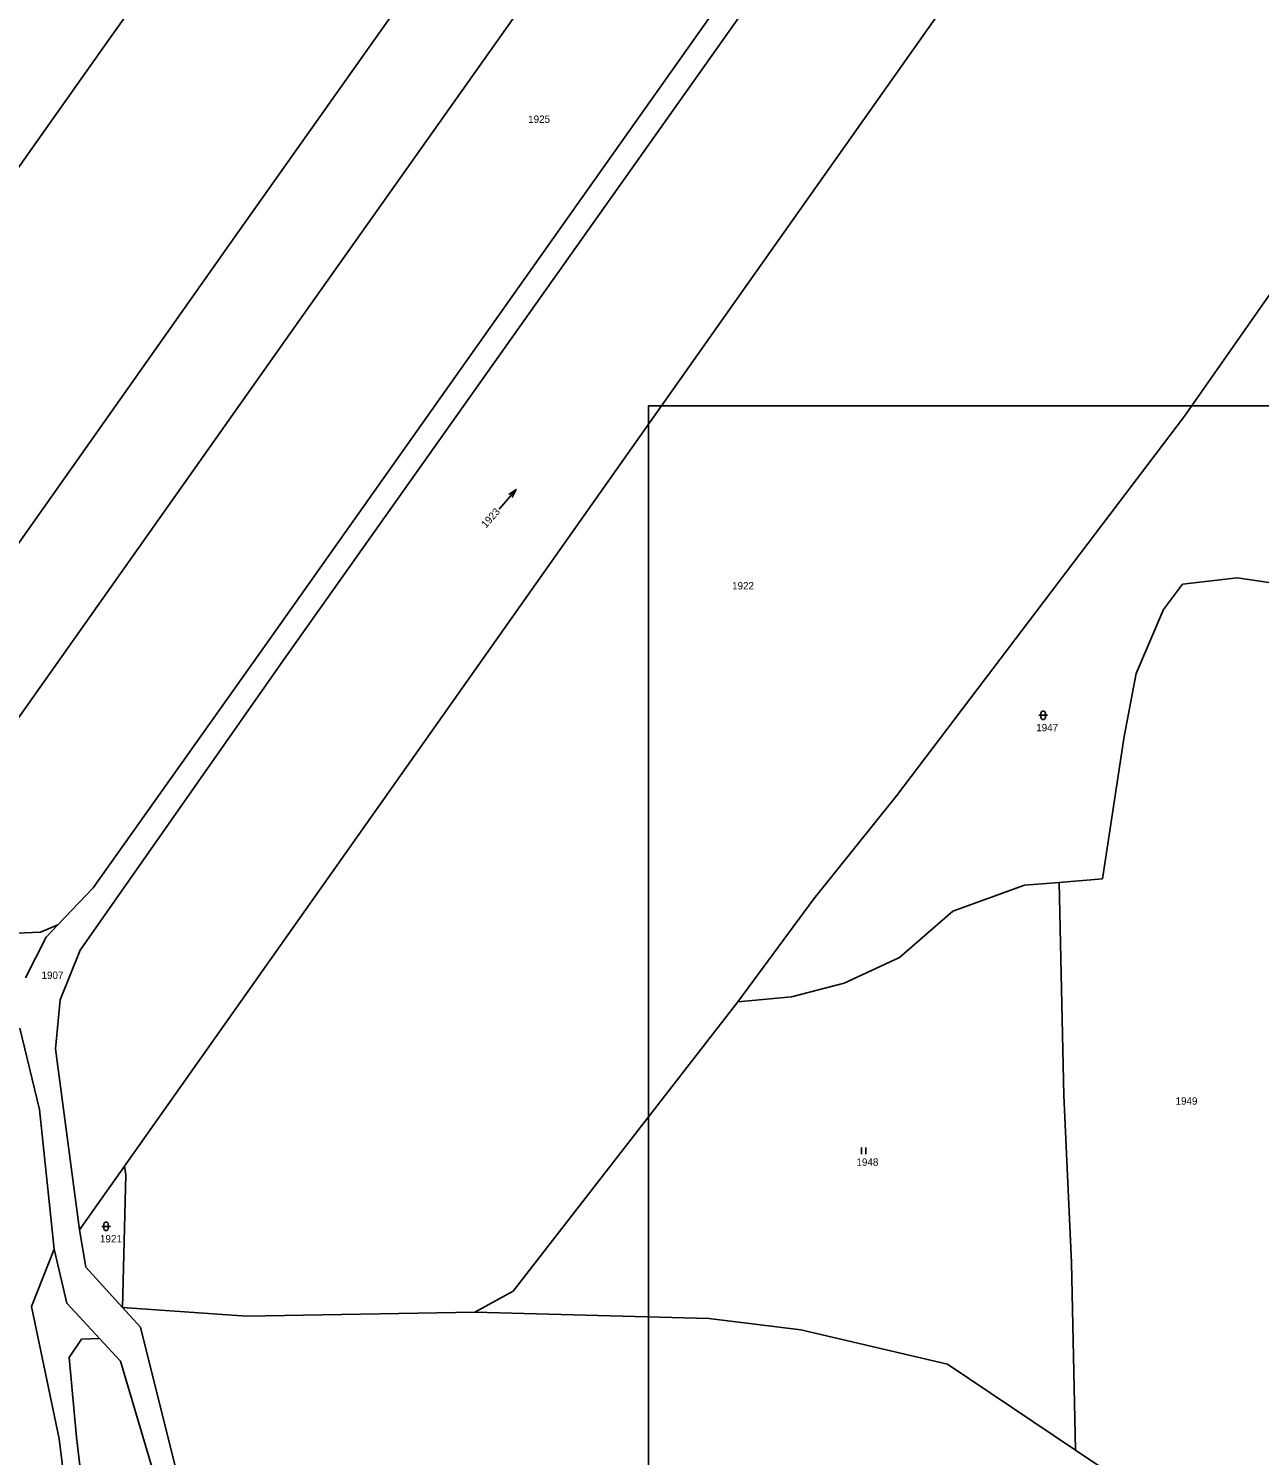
# Model space of a CAD drawing. Extents: x -801853 to -800578, y -1017479 to -1016338.
# Drawn here: x -801702.3 to -801418.1, y -1016987.3 to -1016658 of the extents above; entities that cross this region are included whole.
import ezdxf

# ---------------------------------------------------------------- set-up
doc = ezdxf.new("R2010")
doc.units = 0
for name, color, linetype in [('Default', 7, 'Continuous'), ('KN_HRANICE', 7, 'Continuous'), ('KN_KULTURY', 7, 'Continuous'), ('KN_PARCELY', 7, 'Continuous'), ('LEGENDA', 7, 'Continuous')]:
    doc.layers.add(name, color=color, linetype=linetype)

# ---------------------------------------------------------------- blocks, each defined once
blk = doc.blocks.new('306')
at = {"layer": 'Default'}
for p, q in [((-0.5, 1.5), (-0.5, 0)), ((0.5, 0), (0.5, 1.5))]:
    blk.add_line(p, q, dxfattribs=at)
blk = doc.blocks.new('316')
at = {"layer": 'Default'}
for points in [[(-1, 1), (0.27, 1), (1, 1)], [(-0.5, 1.5), (-0.4, 1.79), (-0.15, 1.97), (0.16, 1.97), (0.41, 1.79), (0.51, 1.5), (0.51, 0.5), (0.41, 0.21), (0.16, 0.03), (-0.15, 0.03), (-0.4, 0.21), (-0.5, 0.5), (-0.5, 1.5)]]:
    blk.add_lwpolyline(points, dxfattribs=at)
blk = doc.blocks.new('802')
at = {"layer": 'Default'}
blk.add_line((-3, 0), (3, 0), dxfattribs=at)
blk.add_lwpolyline([(1, 0.5), (3, 0), (1, -0.5)], dxfattribs=at)

msp = doc.modelspace()

# ---------------------------------------------------------------- linework, layer by layer
at = {"layer": 'KN_HRANICE'}
for p, q in [((-801683.77, -1016660.64), (-801596.87, -1016538.03)), ((-801653.68, -1016704.77), (-801566.87, -1016582.04)), ((-801447.6, -1016591.37), (-801541.38, -1016724.15)), ((-801639.69, -1016725.29), (-801552.88, -1016602.56)), ((-801575.59, -1016698.58), (-801517.05, -1016615.83)), ((-801571.59, -1016702.44), (-801511.85, -1016618.06)), ((-801760.35, -1016768.65), (-801683.77, -1016660.64)), ((-801647.38, -1016800.06), (-801575.59, -1016698.58)), ((-801643.1, -1016803.32), (-801571.59, -1016702.44)), ((-801734.03, -1016818.37), (-801653.68, -1016704.77)), ((-801435.35, -1016747.43), (-801414.37, -1016717.41)), ((-801721.83, -1016841.42), (-801639.69, -1016725.29)), ((-801541.38, -1016724.15), (-801613.25, -1016825.92)), ((-801435.35, -1016747.43), (-801501.91, -1016835.06)), ((-801435.81, -1016786.18), (-801423.24, -1016784.75)), ((-801423.24, -1016784.75), (-801409.24, -1016786.85)), ((-801440.23, -1016792.04), (-801435.81, -1016786.18)), ((-801446.53, -1016806.87), (-801440.23, -1016792.04)), ((-801687.33, -1016856.32), (-801647.38, -1016800.06)), ((-801690.36, -1016870.7), (-801643.1, -1016803.32)), ((-801449.28, -1016821.35), (-801446.53, -1016806.87)), ((-801454.35, -1016854.21), (-801449.28, -1016821.35)), ((-801613.25, -1016825.92), (-801680.1, -1016920.57)), ((-801501.91, -1016835.06), (-801520.97, -1016858.87)), ((-801695.48, -1016864.85), (-801687.33, -1016856.32)), ((-801488.84, -1016861.66), (-801472.31, -1016855.72)), ((-801472.31, -1016855.72), (-801464.32, -1016855.05)), ((-801464.32, -1016855.05), (-801454.35, -1016854.21)), ((-801464.32, -1016855.05), (-801463.26, -1016904.2)), ((-801520.97, -1016858.87), (-801538.54, -1016882.63)), ((-801501.16, -1016872.36), (-801488.84, -1016861.66)), ((-801705.06, -1016866.78), (-801699.53, -1016866.51)), ((-801695.48, -1016864.85), (-801699.53, -1016866.51)), ((-801698.22, -1016867.71), (-801695.48, -1016864.85)), ((-801702.94, -1016877.09), (-801698.22, -1016867.71)), ((-801694.95, -1016882.15), (-801690.36, -1016870.7)), ((-801513.97, -1016878.29), (-801501.16, -1016872.36)), ((-801526.09, -1016881.45), (-801513.97, -1016878.29)), ((-801696.06, -1016893.49), (-801694.95, -1016882.15)), ((-801590.36, -1016949.37), (-801538.54, -1016882.63)), ((-801538.54, -1016882.63), (-801526.09, -1016881.45)), ((-801699.73, -1016907.45), (-801704.27, -1016888.67)), ((-801690.47, -1016935.25), (-801696.06, -1016893.49)), ((-801463.26, -1016904.2), (-801461.44, -1016942.77)), ((-801696.36, -1016939.74), (-801699.73, -1016907.45)), ((-801680.1, -1016920.57), (-801690.47, -1016935.25)), ((-801680.56, -1016953.19), (-801679.8, -1016922.57)), ((-801679.8, -1016922.57), (-801680.1, -1016920.57)), ((-801689.06, -1016943.83), (-801690.47, -1016935.25)), ((-801696.36, -1016939.74), (-801701.6, -1016952.9)), ((-801693.42, -1016952.2), (-801696.36, -1016939.74)), ((-801461.44, -1016942.77), (-801460.58, -1016986.09)), ((-801680.56, -1016953.19), (-801689.06, -1016943.83)), ((-801599.25, -1016954.23), (-801590.36, -1016949.37)), ((-801701.6, -1016952.9), (-801695.19, -1016983.45)), ((-801685.92, -1016960.3), (-801693.42, -1016952.2)), ((-801676.44, -1016957.72), (-801680.56, -1016953.19)), ((-801680.56, -1016953.19), (-801651.92, -1016955.2)), ((-801651.92, -1016955.2), (-801599.25, -1016954.23)), ((-801545.22, -1016955.68), (-801599.25, -1016954.23)), ((-801523.93, -1016958.35), (-801545.22, -1016955.68)), ((-801661.3, -1017018.39), (-801676.44, -1016957.72)), ((-801490.1, -1016966.21), (-801523.93, -1016958.35)), ((-801692.86, -1016964.69), (-801690.07, -1016960.49)), ((-801690.07, -1016960.49), (-801685.92, -1016960.3)), ((-801681.07, -1016965.55), (-801685.92, -1016960.3)), ((-801691.2, -1016983.13), (-801692.86, -1016964.69)), ((-801673.18, -1016992.05), (-801681.07, -1016965.55)), ((-801460.58, -1016986.09), (-801490.1, -1016966.21)), ((-801692.25, -1017007.35), (-801695.19, -1016983.45)), ((-801688.27, -1017006.93), (-801691.2, -1016983.13)), ((-801460.58, -1016986.09), (-801454.5, -1016990.2))]:
    msp.add_line(p, q, dxfattribs=at)
at = {"layer": 'LEGENDA'}
msp.add_lwpolyline([(-801559.16, -1017339.08), (-800718.16, -1017339.08), (-800718.16, -1016745.08), (-801559.16, -1016745.08)], close=True, dxfattribs=at)

# ---------------------------------------------------------------- block references
at = {"layer": 'KN_KULTURY', "rotation": 49.56084899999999}
msp.add_blockref('802', (-801591.64, -1016766.64), dxfattribs=at)
at = {"layer": 'KN_KULTURY'}
for name, p in [('316', (-801468.02, -1016817.47)), ('306', (-801509.47, -1016917.76)), ('316', (-801684.38, -1016935.45))]:
    msp.add_blockref(name, p, dxfattribs=at)

# ---------------------------------------------------------------- texts
at = {"layer": 'KN_PARCELY'}
for s, p in [('1925', (-801586.92, -1016679.74)), ('1922', (-801539.83, -1016787.43)), ('1947', (-801469.62, -1016820.17)), ('1907', (-801699.27, -1016877.33)), ('1949', (-801437.45, -1016906.35)), ('1948', (-801511.12, -1016920.46)), ('1921', (-801685.77, -1016938.15))]:
    msp.add_text(s, height=1.7, dxfattribs=at).set_placement(p)
msp.add_text('1923', height=1.7, rotation=48.472, dxfattribs=at).set_placement((-801596.64, -1016773.36))

doc.saveas('drawing.dxf')
